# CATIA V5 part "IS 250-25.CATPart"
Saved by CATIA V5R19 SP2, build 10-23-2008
Part number: IS 250-25
Bounding box of the stored display mesh (mm): x -18.951 to 18.951, y -18.952 to 18.952, z 0 to 100
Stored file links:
  C:\Users\Bora\Desktop\3D Katı model\IS serisi\IS 250\IS 250-25.CATPart
  C:\Program Files\Dassault Systemes\B19\intel_a\reffiles\standard\MetricThickPitch.txt
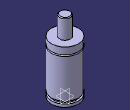
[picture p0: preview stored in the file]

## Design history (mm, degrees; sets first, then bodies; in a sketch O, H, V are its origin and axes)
Body1 (main body)
  Sketch1 on yz-plane, origin (0, 0, 0), H (0, 1, 0), V (0, 0, 1)
    point P3 (7.5, 99)
    point P5 (7.5, 99)
    point P7 (19, 63.5)
    point P8 (19, 61.5)
    point P12 (19, 61.5)
    point P13 (19, 63.5)
    line L1 (19, 0) -> (19, 4)
    line L2 (7.5, 99) -> (7.5, 73)
    arc A1 centre (6.5, 99) radius 1 from (7.5, 99) to (6.5, 100) ccw
    arc A2 centre (19, 62.5) radius 1 from (19, 63.5) to (19, 61.5) ccw
    line L3 (16.5, 7.5) -> (16.5, 4)
    line L4 (19, 7.5) -> (19, 61.5)
    line L5 (19, 63.5) -> (19, 73)
    line L6 (6.5, 100) -> (0, 100)
    point P15 (0, 100)
    line L7 (7.5, 73) -> (19, 73)
    line L8 (0, 0) -> (19, 0)
    line L9 (16.5, 4) -> (19, 4)
    line L10 (16.5, 7.5) -> (19, 7.5)
    tangency: L6 A1
    coincidence: P15 V, P3 P5, P7 P13, P8 P12
    horizontal: L7 H, L8 H, L9 H, L10 H
  Shaft1: profile Sketch1, axis Sketch1.V, angle 360
  Sketch2 on face of Shaft1 from Sketch1.L8, origin (0, 0, 0), H (1, 0, 0), V (0, -1, 0)
    point P1 (0, 0)
  Hole1: placed by Sketch2, at (0, 0, 0) direction (0, 0, 1), diameter 6.647, depth 7, threaded "M8", thread diameter 8, thread depth 7, pitch 1.25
